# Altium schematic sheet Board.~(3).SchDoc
size A4
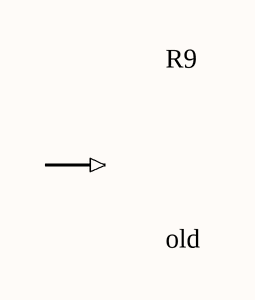
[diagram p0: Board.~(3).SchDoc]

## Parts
R9  old

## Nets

Not connected (* = marked no-connect by the designer): R9 1

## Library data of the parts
R9 = Part0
